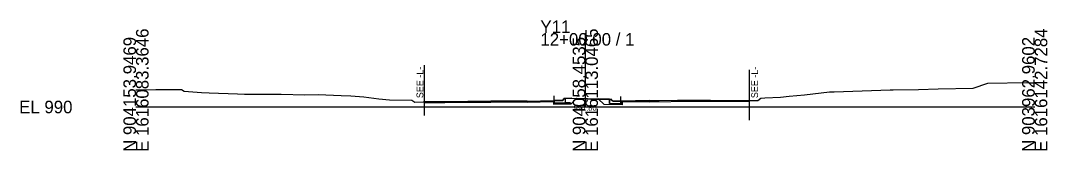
# Model space of a CAD drawing. Extents: x -26 to 203, y -10 to 2019.
# Drawn here: x -25.7 to 202.8, y 1990.3 to 2019.3 of the extents above; entities that cross this region are included whole.
import ezdxf

# ---------------------------------------------------------------- set-up
doc = ezdxf.new("R2010")
doc.units = 0
for name, color, linetype in [('Exist Cross Section Cell', 7, 'Continuous'), ('Exist XS Center Line Elevation Label', 7, 'Continuous'), ('Exist XS Ground Line', 7, 'Continuous'), ('Prop XS Earthwork Shape', 7, 'Continuous'), ('Prop XS EOT Tick Mark', 7, 'Continuous'), ('Prop XS Finish Grade', 7, 'Continuous'), ('Prop XS Finish Grade CurbGutter', 7, 'Continuous'), ('Prop XS Finish Grade Earthwork', 7, 'Continuous'), ('Prop XS Finish Grade Pavement', 7, 'Continuous'), ('Prop XS Pvmt Edge Slope', 7, 'Continuous'), ('Prop XS Side Slope Text', 7, 'Continuous'), ('Prop XS Subgrade CurbGutter', 7, 'Continuous'), ('Prop XS Subgrade Earthwork', 7, 'Continuous')]:
    doc.layers.add(name, color=color, linetype=linetype)

msp = doc.modelspace()

# ---------------------------------------------------------------- linework, layer by layer
at = {"layer": 'Exist Cross Section Cell'}
for p, q in [((100, 2000), (100, 2016.47)), ((0, 2000), (100, 2000)), ((100, 2000), (200, 2000))]:
    msp.add_line(p, q, dxfattribs=at)
at = {"layer": 'Exist XS Ground Line'}
for p, q in [((186.32, 2004.21), (189.59, 2005.33)), ((189.59, 2005.33), (198.25, 2005.46)), ((198.25, 2005.46), (198.7, 2005.38)), ((198.7, 2005.38), (200, 2005.39)), ((0, 2003.79), (2, 2003.83)), ((2, 2003.83), (4.38, 2003.86)), ((4.38, 2003.86), (10.1, 2003.9)), ((10.1, 2003.9), (10.74, 2003.55)), ((10.74, 2003.55), (14.58, 2003.24)), ((14.58, 2003.24), (16.29, 2003.13)), ((16.29, 2003.13), (22.61, 2002.9)), ((22.61, 2002.9), (24.12, 2002.88)), ((24.12, 2002.88), (24.93, 2002.89)), ((24.93, 2002.89), (32.28, 2002.84)), ((32.28, 2002.84), (37.6, 2002.74)), ((37.6, 2002.74), (40.55, 2002.75)), ((40.55, 2002.75), (45.65, 2002.55)), ((45.65, 2002.55), (47.79, 2002.46)), ((47.79, 2002.46), (50.72, 2002.25)), ((50.72, 2002.25), (54.05, 2001.85)), ((94.85, 2001.49), (95.48, 2001.99)), ((95.48, 2001.99), (100, 2001.8)), ((138.39, 2001.45), (139.06, 2001.97)), ((139.06, 2001.97), (139.92, 2002.05)), ((139.92, 2002.05), (143.42, 2002.16)), ((143.42, 2002.16), (145.35, 2002.38)), ((145.35, 2002.38), (148.78, 2002.73)), ((148.78, 2002.73), (154.35, 2003.35)), ((154.35, 2003.35), (155.36, 2003.41)), ((155.36, 2003.41), (167.86, 2003.82)), ((167.86, 2003.82), (168.5, 2003.83)), ((168.5, 2003.83), (174.12, 2003.9)), ((174.12, 2003.9), (178.55, 2004.07)), ((178.55, 2004.07), (186.32, 2004.21)), ((54.05, 2001.85), (56.42, 2001.59)), ((56.42, 2001.59), (61.36, 2001.5)), ((61.36, 2001.5), (62.02, 2001.04)), ((62.02, 2001.04), (63.9, 2001.14)), ((63.9, 2001.14), (64.24, 2001.14)), ((64.24, 2001.14), (68.73, 2001.18)), ((68.73, 2001.18), (79, 2001.28)), ((79, 2001.28), (87.05, 2001.3)), ((87.05, 2001.3), (92.89, 2001.45)), ((92.89, 2001.45), (93.78, 2001.48)), ((93.78, 2001.48), (94.85, 2001.49)), ((100, 2001.8), (101.19, 2001.74)), ((101.19, 2001.74), (105.66, 2001.68)), ((105.66, 2001.68), (106.28, 2001.26)), ((106.28, 2001.26), (106.94, 2001.27)), ((106.94, 2001.27), (108.18, 2001.32)), ((108.18, 2001.32), (120.53, 2001.5)), ((120.53, 2001.5), (123.73, 2001.55)), ((123.73, 2001.55), (127.85, 2001.52)), ((127.85, 2001.52), (136.51, 2001.48)), ((136.51, 2001.48), (137.8, 2001.44)), ((137.8, 2001.44), (138.39, 2001.45))]:
    msp.add_line(p, q, dxfattribs=at)
at = {"layer": 'Prop XS Earthwork Shape'}
for points in [[(95.34, 2001.9), (95.48, 2001.99), (96.98, 2001.93), (95.59, 2001.9)], [(98.05, 2001.88), (98.13, 2001.95), (102.88, 2001.8), (102.96, 2001.72), (101.19, 2001.74), (100, 2001.8)], [(92.89, 2000.63), (96.84, 2000.67), (96.59, 2000.91), (95.59, 2000.9), (93.09, 2000.88), (93.09, 2001.46), (92.89, 2001.45)], [(95.59, 2000.9), (95.59, 2001.9), (95.34, 2001.9), (95.1, 2001.69), (95.06, 2001.52), (94.96, 2001.43), (94.84, 2001.41), (93.09, 2001.46), (93.09, 2000.88)], [(93.09, 2001.46), (93.78, 2001.48), (94.85, 2001.49), (95.1, 2001.69), (95.06, 2001.52), (94.96, 2001.43), (94.84, 2001.41)], [(96.98, 2001.93), (98.05, 2001.88), (96.84, 2000.67), (96.59, 2000.91), (95.59, 2000.9), (95.59, 2001.9)], [(102.96, 2001.72), (105.41, 2001.69), (105.41, 2000.75), (107.91, 2000.73), (107.91, 2001.31), (108.18, 2001.32), (108.18, 2000.47), (104.16, 2000.52)], [(106.28, 2001.26), (106.16, 2001.26), (106.04, 2001.28), (105.95, 2001.37), (105.91, 2001.52), (105.66, 2001.68), (105.41, 2001.69), (105.41, 2000.75), (107.91, 2000.73), (107.91, 2001.31), (106.94, 2001.27), (106.48, 2001.26)], [(106.28, 2001.26), (106.16, 2001.26), (106.04, 2001.28), (105.95, 2001.37), (105.91, 2001.52)]]:
    msp.add_lwpolyline(points, close=True, dxfattribs=at)
at = {"layer": 'Prop XS EOT Tick Mark'}
for p, q in [((64.24, 1998.11), (64.24, 2009.32)), ((136.51, 1997.07), (136.51, 2008.28)), ((93.09, 2001.46), (93.09, 2002.46)), ((107.91, 2001.31), (107.91, 2002.31))]:
    msp.add_line(p, q, dxfattribs=at)
at = {"layer": 'Prop XS Finish Grade'}
for p, q in [((95.59, 2001.9), (98.13, 2001.95)), ((105.41, 2001.75), (102.88, 2001.8))]:
    msp.add_line(p, q, dxfattribs=at)
at = {"layer": 'Prop XS Finish Grade CurbGutter'}
for p, q in [((93.09, 2001.46), (94.84, 2001.41)), ((94.84, 2001.41), (94.96, 2001.43)), ((94.96, 2001.43), (95.06, 2001.52)), ((95.06, 2001.52), (95.12, 2001.77)), ((95.12, 2001.77), (95.21, 2001.86)), ((95.34, 2001.9), (95.21, 2001.86)), ((95.59, 2001.9), (95.34, 2001.9)), ((105.41, 2001.75), (105.66, 2001.75)), ((105.66, 2001.75), (105.79, 2001.71)), ((105.88, 2001.62), (105.79, 2001.71)), ((105.95, 2001.37), (105.88, 2001.62)), ((106.04, 2001.28), (105.95, 2001.37)), ((106.16, 2001.26), (106.04, 2001.28)), ((107.91, 2001.31), (106.16, 2001.26))]:
    msp.add_line(p, q, dxfattribs=at)
at = {"layer": 'Prop XS Finish Grade Earthwork'}
msp.add_line((98.13, 2001.95), (102.88, 2001.8), dxfattribs=at)
at = {"layer": 'Prop XS Finish Grade Pavement'}
for p, q in [((68.73, 2001.18), (64.24, 2001.14)), ((68.74, 2000.93), (64.25, 2000.89)), ((79, 2001.28), (68.73, 2001.18)), ((79, 2001.03), (68.74, 2000.93)), ((87.05, 2001.3), (79, 2001.28)), ((87.05, 2001.05), (79, 2001.03)), ((87.05, 2001.3), (93.09, 2001.46)), ((87.05, 2001.05), (92.89, 2001.2)), ((114.36, 2001.41), (107.91, 2001.31)), ((114.36, 2001.16), (107.92, 2001.06)), ((114.36, 2001.41), (123.73, 2001.55)), ((114.36, 2001.16), (123.74, 2001.3)), ((123.73, 2001.55), (136.51, 2001.48)), ((123.73, 2001.3), (136.51, 2001.23))]:
    msp.add_line(p, q, dxfattribs=at)
at = {"layer": 'Prop XS Pvmt Edge Slope'}
for p, q in [((95.59, 2000.9), (96.59, 2000.91)), ((96.59, 2000.91), (96.84, 2000.67))]:
    msp.add_line(p, q, dxfattribs=at)
at = {"layer": 'Prop XS Subgrade CurbGutter'}
for p, q in [((93.09, 2001.46), (93.09, 2000.88)), ((93.09, 2000.88), (95.59, 2000.9)), ((95.59, 2000.9), (95.59, 2001.9)), ((105.41, 2000.75), (105.41, 2001.75)), ((107.91, 2000.73), (105.41, 2000.75)), ((107.91, 2001.31), (107.91, 2000.73))]:
    msp.add_line(p, q, dxfattribs=at)
at = {"layer": 'Prop XS Subgrade Earthwork'}
for p, q in [((96.84, 2000.67), (98.13, 2001.95)), ((92.89, 2001.45), (92.89, 2000.63)), ((92.89, 2000.63), (96.84, 2000.67)), ((102.88, 2001.8), (104.16, 2000.52)), ((108.18, 2000.47), (104.16, 2000.52)), ((108.18, 2001.32), (108.18, 2000.47))]:
    msp.add_line(p, q, dxfattribs=at)

# ---------------------------------------------------------------- texts
at = {"layer": 'Exist Cross Section Cell'}
for s, p in [('Y11', (90, 2016.47)), ('12+00.00 / 1', (90, 2013.67)), ('EL 990', (-26, 1998.6))]:
    msp.add_text(s, height=2.8, dxfattribs=at).set_placement(p)
for s, p in [('E 1616083.3646', (2.8, 1990)), ('E 1616113.0465', (102.8, 1990)), ('E 1616142.7284', (202.8, 1990)), ('N 904153.9469', (0, 1990)), ('N 904058.4535', (100, 1990)), ('N 903962.9602', (200, 1990))]:
    msp.add_text(s, height=2.8, rotation=90, dxfattribs=at).set_placement(p)
at = {"layer": 'Exist XS Center Line Elevation Label'}
msp.add_text('991.80', height=1.25, dxfattribs=at).set_placement((97.4, 1999.17))
at = {"layer": 'Prop XS Side Slope Text'}
for p in [(63.93, 2001.96), (138.42, 2001.96)]:
    msp.add_text('SEE -L-', height=1.5, rotation=90, dxfattribs=at).set_placement(p)

doc.saveas('drawing.dxf')
